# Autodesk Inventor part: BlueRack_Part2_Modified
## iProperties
Shininess: 64.0
Length Units: 11272
Angle Units: 11279
Time Units: 11290
Mass Units: 11286
Length Display Precision: 3
Angle Display Precision: 2
Compacted: True
Part Number: BlueRack_Part2_Modified
Document SubType Name: Modeling
Created: 2004-12
Designer: John Blackburn
Material: Steel, Mild
Manufacturer: Standard
Standards Organization: Custom
Density: 0.0
Volumn: 0.0
Area: 0.0
PropertySet Name: Model Information
Control State: 0
Master: False
Checked Out: False
Author: John Blackburn
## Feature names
1. Extrusion1
2. Hole1
3. Hole3
4. Rectangular Pattern3
5. Hole4
6. Rectangular Pattern4
7. Rectangular Pattern5
